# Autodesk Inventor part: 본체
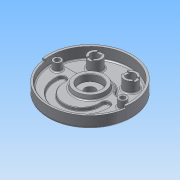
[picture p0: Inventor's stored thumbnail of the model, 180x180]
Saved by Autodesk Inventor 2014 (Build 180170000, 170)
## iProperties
Created: 2015-06
Part Number: 본체
Material: 알루미늄 6061
Document SubType Name: Modeling
Designer: Administrator
Density: 2.71 g/cm^3
Appearance: 알루미늄 - 평지
Mass: 1070.21 g
Surface Area: 1030.16 cm^2
Volume: 394.913 cm^3
Author: Administrator
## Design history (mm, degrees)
sketch "스케치1"
  geometry: C1 r 95 at (0, 0); 1 further point
  constraints: 1 centre point, 1 coincident
  dimensions: "d0" = 190 diameter of C1
extrude "돌출1" new body sketch "스케치1" distance "d1" = 32; taper "d2" = 0 deg
sketch "스케치2"
  geometry: L1 (45.033, 16)-(75.657, 16); L2 (-45.033, 16)-(-75.657, 16); L3 (0, 0)-(-95, 0); L4 (0, 0)-(95, 0); L5 (0, 0)-(-94.075, -13.221); L6 (0, 0)-(94.075, -13.221); C1 r 90 at (0, 0); A1 r 95 centre (0, 0) between (-95, 0) and (95, 0) reference; A2 r 90 centre (0, 0) between (85.114, 29.25) and (-85.114, 29.25); A3 r 42 centre (0, 0) between (36.373, 21) and (-36.373, 21); A4 r 10 centre (-75.657, 26) between (-85.114, 29.25) and (-75.657, 16); A5 r 10 centre (-45.033, 26) between (-45.033, 16) and (-36.373, 21); A6 r 10 centre (45.033, 26) between (36.373, 21) and (45.033, 16); A7 r 10 centre (75.657, 26) between (75.657, 16) and (85.114, 29.25); 4 further points
  constraints: 20 point on circle, 12 end point, 8 tangent, 7 centre point, 4 point on line, 3 coincident, 3 collinear, 2 equal radius, 1 horizontal, 1 parallel
  dimensions: "d3" = 180 diameter of A2; "d4" = 84 diameter of A3; "d5" = 16 distance from line of A1.centre L2; "d6" = 10 radius of A4; "d7" = 10 radius of A5; "d15" = 180 diameter of C1; "d43" = 8 deg angle of L5 L3; "d44" = 8 deg angle of L6 L4
extrude "돌출2" cut sketch "스케치2" distance "d9" = 25; taper "d10" = 0 deg
sketch "스케치3"
  geometry: C1 r 95 at (0, 0) reference; C2 r 26 at (0, 0)
  constraints: 1 centre point, 1 coincident
  dimensions: "d11" = 52 diameter of C2
extrude "돌출3" join sketch "스케치3" distance "d12" = 12; taper "d13" = -15 deg
extrude "돌출4" cut sketch "스케치2" distance "d16" = 18; taper "d17" = 0 deg
sketch "스케치4"
  geometry: C1 r 42 at (0, 0); C2 r 35 at (0, 0); A1 r 42 centre (0, 0) between (36.373, 21) and (-36.373, 21) reference
  constraints: 2 centre point, 2 coincident
  dimensions: "d18" = 84 diameter of C1; "d19" = 70 diameter of C2
extrude "돌출5" join sketch "스케치4" distance "d20" = 10; taper "d21" = -10 deg
sketch "스케치5"
  geometry: C1 r 35 at (0, 0) reference; A1 r 9 centre (49.749, -14) between (58.704, -13.1) and (40.794, -14.9); A2 r 9 centre (-49.749, -14) between (-40.794, -14.9) and (-58.704, -13.1); A3 r 59 centre (0, -19) between (-58.704, -13.1) and (58.704, -13.1); A4 r 41 centre (0, -19) between (-40.794, -14.9) and (40.794, -14.9)
  constraints: 8 point on circle, 4 centre point, 3 tangent, 1 coincident, 1 equal radius, 1 horizontal alignment, 1 vertical alignment
  dimensions: "d22" = 19 distance of A3.centre C1.centre; "d23" = 118 diameter of A3; "d24" = 82 diameter of A4; "d25" = 5 vertical distance of A3.centre A1.centre
extrude "돌출6" cut sketch "스케치5" distance "d26" = 7; taper "d27" = 0 deg
sketch "스케치6"
  geometry: C1 r 15 at (-40, 52); C2 r 15 at (40, 52); A1 r 42 centre (0, 0) between (36.373, 21) and (-36.373, 21) reference
  constraints: 2 centre point, 1 equal radius, 1 horizontal alignment
  dimensions: "d28" = 52 vertical distance of C2.centre A1.centre; "d29" = 30 diameter of C2; "d30" = 80 distance of C2.centre C1.centre; "d31" = 40 horizontal distance of C2.centre A1.centre
extrude "돌출7" join sketch "스케치6" stored distance "d32" = 7; taper "d33" = 0 deg
sketch "스케치7"
  geometry: C1 r 35 at (0, 0) reference; C2 r 9 at (-74, 0); C3 r 9 at (74, 0)
  constraints: 2 centre point, 2 horizontal alignment, 1 equal radius
  dimensions: "d34" = 18 diameter of C2; "d35" = 148 distance of C3.centre C2.centre; "d36" = 74 distance of C2.centre C1.centre
extrude "돌출8" join sketch "스케치7" stored distance "d37" = 7; taper "d38" = 0 deg
sketch "스케치9"
  geometry: L1 (0, 0)-(-95, 0); L2 (0, 0)-(95, 0); L3 (0, 0)-(-94.075, -13.221); L4 (0, 0)-(94.075, -13.221); C1 r 90 at (0, 0) reference; A1 r 95 centre (0, 0) between (-95, 0) and (95, 0) reference
  constraints: 8 end point, 4 point on circle, 1 collinear, 1 horizontal
  dimensions: "d45" = 8 deg angle of L1 L3; "d46" = 8 deg angle of L2 L4
extrude "돌출9" cut sketch "스케치9" distance "d47" = 5; taper "d48" = 0 deg
hole "구멍1" diameter "d51" = 23; stored, may be unused: countersink angle "d55" = 90 deg, drill point angle "d57" = 118 deg; dims "d49" = 10, "d50" = 10, "d52" = 6, "d53" = 50, "d54" = 15, "d56" = 8
hole "구멍2" diameter "d60" = 20; stored, may be unused: countersink angle "d64" = 90 deg, drill point angle "d66" = 118 deg; dims "d58" = 10, "d59" = 10, "d61" = 6, "d62" = 50, "d63" = 15, "d65" = 8
hole "구멍3" diameter "d69" = 20; stored, may be unused: countersink angle "d73" = 90 deg, drill point angle "d75" = 118 deg; dims "d67" = 10, "d68" = 10, "d70" = 6, "d71" = 50, "d72" = 15, "d74" = 8
sketch "스케치10"
  geometry: C1 r 9 at (-74, 0) reference; C2 r 9 at (74, 0) reference; 2 further points
  constraints: 2 coincident
hole "구멍4" sketch "스케치10" at (-74, 0), (74, 0) diameter "d76" = 11; stored, may be unused: countersink angle "d80" = 90 deg, drill point angle "d82" = 118 deg; dims "d77" = 6, "d78" = 18, "d79" = 11, "d81" = 8
sketch "스케치11"
  geometry: L1 (-6, 13.748)-(-6, -13.748); L2 (6, 13.748)-(6, -13.748); L3 (66.252, 6)-(93.748, 6); L4 (93.748, -6)-(66.252, -6); C1 r 10 at (0, 0) reference; C2 r 10 at (80, 0) reference; A1 r 15 centre (0, 0) between (-6, 13.748) and (-6, -13.748) reference; A2 r 15 centre (80, 0) between (66.252, 6) and (93.748, 6) reference; 1 further point
  constraints: 8 end point, 8 point on circle, 2 parallel, 1 perpendicular, 1 vertical
  dimensions: "d83" = 12 distance between parallel lines of L2 L1; "d84" = 6 distance from line of L1 C1.centre; "d85" = 12 distance between parallel lines of L4 L3; "d86" = 6 distance from line of L3 C2.centre
extrude "돌출10" cut sketch "스케치11" distance "d87" = 3; taper "d88" = 0 deg
fillet "모깎기1" dims "d89" = 5
fillet "모깎기2" dims "d90" = 3, "d91" = 1, "d92" = 0.3
chamfer "모따기1" distance "d93" = 1; stored, may be unused: second distance "d94" = 2, angle "d95" = 45 deg
sketch "스케치12"
  geometry: C1 r 28.302 at (0, 0) reference; C2 r 68 at (0, 0)
  constraints: 1 centre point, 1 coincident, 1 other
  dimensions: "d96" = 136 diameter of C2
feature "엠보싱1" sketch "스케치12" dims "d97" = 0.5, "d98" = 0
fillet "모깎기3" dims "d99" = 3
node "솔리드1"
node "투영된 루프1"
